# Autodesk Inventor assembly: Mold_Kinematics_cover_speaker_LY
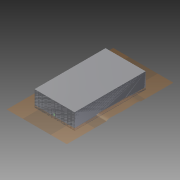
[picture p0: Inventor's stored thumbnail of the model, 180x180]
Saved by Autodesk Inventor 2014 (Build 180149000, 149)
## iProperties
Created: 2009-12
Part Number: Mold_Kinematics_cover_speaker_LY
Document SubType Name: Assembly
Designer: gaom
Author: gaom
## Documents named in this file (2)
- C:\Users\iTools\Desktop\tutorial files\Mold\Mold Kinematics\Mold_Kinematics_cover_speaker_LY.iam
- C:\Users\iTools\Desktop\tutorial files\Mold\Mold Kinematics\Mold_Kinematics_cover_speaker_PZ.iam
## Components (1 placed, 1 different names)
1. Mold_Kinematics_cover_speaker_PZ:1 [sub-assembly] — Flush:1, Flush:2, Flush:3
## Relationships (3: Flush 3)
- Flush:1: Mold_Kinematics_cover_speaker_PZ:1
- Flush:2: Mold_Kinematics_cover_speaker_PZ:1
- Flush:3: Mold_Kinematics_cover_speaker_PZ:1
